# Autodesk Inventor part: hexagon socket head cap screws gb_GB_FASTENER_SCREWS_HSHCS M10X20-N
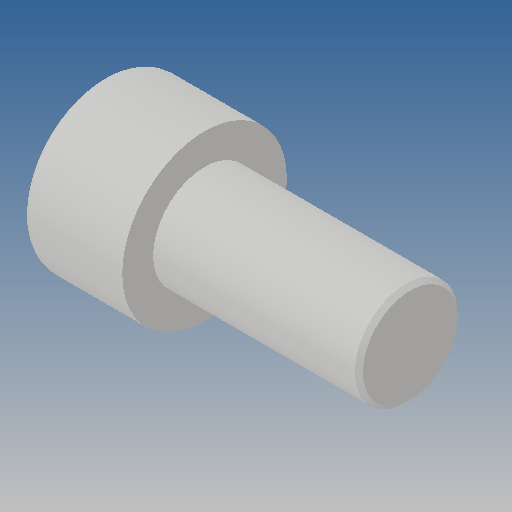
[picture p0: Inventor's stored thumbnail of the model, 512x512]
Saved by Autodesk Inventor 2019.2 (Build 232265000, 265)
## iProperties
Created: 2013-04
Part Number: hexagon socket head cap screws gb_GB_FASTENER_SCREWS_HSHCS M10X20-N
Material: Ogólny
Document SubType Name: Modeling
Designer: CADENGINEERING4
Density: 1 g/cm^3
Appearance: Domyślna
Author: CADENGINEERING4
Revision Number: ÈÎºÎ
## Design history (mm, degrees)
chamfer "Chamfer1"
node "Bryła1"
